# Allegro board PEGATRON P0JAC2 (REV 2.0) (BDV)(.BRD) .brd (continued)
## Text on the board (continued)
L6-GND: list("[Spacing] L6-GND" "43.Microvia to Route Keepout" "0 MIL [DEFAULT]" "OVERLAP" "" "DRC ERROR CLASS/L6-GND" "[Shape] Route Keepout/All ((-570.0 2225.0) (410.0 2765.0))" "[B/BVia] AU_HP_L (VIA10D4A24-L6-L7) (-535.72 2513.77)" list(-532.440000 2510.000000) nil)@@@list("bobo_dong" "2014/01/13 20:47:23" nil "S0DCOA89102" "g1t-p0jac.11")@@@nil | list("[Spacing] L6-GND" "40.Microvia to Route Keepout" "0 MIL [DEFAULT]" "OVERLAP" "" "DRC ERROR CLASS/L6-GND" "[Shape] Route Keepout/All ((-570.0 2225.0) (410.0 2765.0))" "[B/BVia] AGND_AUD (VIA10D4A24-L6-L7) (-535.72 2592.51)" list(-531.380000 2595.000000) nil)@@@list("bobo_dong" "2014/01/13 20:47:18" nil "S0DCOA89102" "g1t-p0jac.11")@@@nil | list("[Spacing] L6-GND" "8.Shape to Route Keepin" "0 MIL [DEFAULT]" "0 MIL" "0.00 MIL" "DRC ERROR CLASS/L6-GND" "[Shape] Route Keepin/All ((-679.03 -19.38) (3281.17 4854.0))" "[L6-Gnd Shape] GND ((-679.11 -19.37) (3281.09 4854.01))" list(-260.500000 4854.000000) nil)@@@nil@@@list("vincent_kuo" "2014/02/26 12:03:45" nil "VINCENT_KUO-PC" "g1t-p0jac_byt-t.14") | list("[Spacing] L6-GND" "3.Shape to Route Keepin" "0 MIL [DEFAULT]" "0 MIL" "0.00 MIL" "DRC ERROR CLASS/L6-GND" "[Shape] Route Keepin/All ((-679.03 -19.38) (3281.17 4854.0))" "[L6-Gnd Shape] GND ((-679.11 -19.37) (3281.09 4854.01))" list(-19.380000 -0.010000) nil)@@@list("bobo_dong" "2014/02/26 15:13:22" nil "S0DCOA89102" "g1t-p0jac.11")@@@list("vincent_kuo" "2014/02/26 15:23:36" nil "VINCENT_KUO-PC" "g1t-p0jac_byt-t.14") | list("[Spacing] L6-GND" "41.Microvia to Route Keepout" "0 MIL [DEFAULT]" "OVERLAP" "" "DRC ERROR CLASS/L6-GND" "[Shape] Route Keepout/All ((-570.0 2225.0) (410.0 2765.0))" "[B/BVia] AGND_AUD (VIA10D4A24-L6-L7) (273.53 2604.1)" list(275.000000 2608.880000) nil)@@@list("bobo_dong" "2014/01/13 20:47:18" nil "S0DCOA89102" "g1t-p0jac.11")@@@nil | list("[Spacing] L6-GND" "42.Thru Via to Route Keepout" "0 MIL [DEFAULT]" "0 MIL" "0.00 MIL" "DRC ERROR CLASS/L6-GND" "[Shape] Route Keepout/All ((-570.0 2225.0) (410.0 2765.0))" "[ThruVia] AU_HP_L (VIA20D10A32) (340.8 2717.6)" list(350.000000 2721.520000) nil)@@@list("bobo_dong" "2014/01/13 20:47:19" nil "S0DCOA89102" "g1t-p0jac.11")@@@nil | list("[Spacing] L6-GND" "37.Line to Route Keepout" "0 MIL [DEFAULT]" "0 MIL" "0.00 MIL" "DRC ERROR CLASS/L6-GND" "[Shape] Route Keepout/All ((155.0 2225.0) (480.0 2457.5))" "[Line] MICBIAS1 ((418.0 2429.68) (427.1 2438.78))" list(420.000000 2431.680000) nil)@@@list("bobo_dong" "2014/01/13 20:47:08" nil "S0DCOA89102" "g1t-p0jac.11")@@@nil | list("[Spacing] L6-GND" "36.Line to Route Keepout" "0 MIL [DEFAULT]" "0 MIL" "0.00 MIL" "DRC ERROR CLASS/L6-GND" "[Shape] Route Keepout/All ((155.0 2225.0) (480.0 2457.5))" "[Line] MICBIAS1 ((418.0 2415.0) (422.0 2433.68))" list(420.000000 2424.340000) nil)@@@list("bobo_dong" "2014/01/13 20:47:05" nil "S0DCOA89102" "g1t-p0jac.11")@@@nil | list("[Spacing] L6-GND" "1.Line to Route Keepout" "0 MIL [DEFAULT]" "0 MIL" "0.00 MIL" "DRC ERROR CLASS/L6-GND" "[Shape] Route Keepout/All ((155.0 2225.0) (480.0 2457.5))" "[Line] MICBIAS1 ((411.0 2408.0) (427.1 2424.1))" list(420.000000 2417.000000) nil)@@@list("bobo_dong" "2014/01/13 20:58:34" nil "S0DCOA89102" "g1t-p0jac.11")@@@nil | list("[Spacing] L6-GND" "35.Line to Route Keepout" "0 MIL [DEFAULT]" "0 MIL" "0.00 MIL" "DRC ERROR CLASS/L6-GND" "[Shape] Route Keepout/All ((155.0 2225.0) (480.0 2457.5))" "[Line] MICBIAS1 ((411.0 2408.0) (422.0 2419.0))" list(420.000000 2417.000000) nil)@@@list("bobo_dong" "2014/01/13 20:47:03" nil "S0DCOA89102" "g1t-p0jac.11")@@@nil | list("[Spacing] L6-GND" "3.BB Via to Route Keepout" "0 MIL [DEFAULT]" "0 MIL" "0.00 MIL" "DRC ERROR CLASS/L6-GND" "[Shape] Route Keepout/All ((155.0 2225.0) (480.0 2457.5))" "[B/BVia] MICBIAS1 (VIA18D8A26-L3-L6) (413.0 2410.0)" list(420.000000 2415.660000) nil)@@@list("bobo_dong" "2014/01/13 20:58:36" nil "S0DCOA89102" "g1t-p0jac.11")@@@nil | list("[Spacing] L6-GND" "39.Microvia to Route Keepout" "0 MIL [DEFAULT]" "0 MIL" "0.00 MIL" "DRC ERROR CLASS/L6-GND" "[Shape] Route Keepout/All ((155.0 2225.0) (480.0 2457.5))" "[B/BVia] MICBIAS1 (VIA10D4A24-L6-L7) (425.1 2436.78)" list(420.950000 2434.000000) nil)@@@list("bobo_dong" "2014/01/13 20:47:17" nil "S0DCOA89102" "g1t-p0jac.11")@@@nil | list("[Spacing] L6-GND" "2.Line to Route Keepout" "0 MIL [DEFAULT]" "0 MIL" "0.00 MIL" "DRC ERROR CLASS/L6-GND" "[Shape] Route Keepout/All ((155.0 2225.0) (480.0 2457.5))" "[Line] MICBIAS1 ((423.1 2420.1) (427.1 2438.78))" list(425.100000 2427.730000) nil)@@@list("bobo_dong" "2014/01/13 20:58:35" nil "S0DCOA89102" "g1t-p0jac.11")@@@nil | list("[Spacing-SameNet] L6-GND" "68.Line to Shape Same Net" "4 MIL [DEFAULT]" "0 MIL" "4.00 MIL" "DRC ERROR CLASS/L6-GND" "[Line] GND ((1181.5 2923.5) (1191.5 2935.5))" "[L6-Gnd Shape] GND ((1179.11 2932.53) (1197.86 2957.97))" list(1190.000000 2934.000000) nil)@@@list("jennifer_hsu" "2014/01/14 11:36:27" nil "JENNIFER_H-PC" "g1t-p0jac_byt-t.11")@@@list("doris_chen" "2014/01/16 14:59:34" nil "JULIA_YU-PC1" "g1t-p0jac_byt-t.13-chk") | list("[Spacing-SameNet] L6-GND" "69.Line to Line Same Net" "4 MIL [DEFAULT]" "3.08 MIL" "0.92 MIL" "DRC ERROR CLASS/L6-GND" "[Line] GND ((1267.5 2921.5) (1273.5 2935.5))" "[Line] GND ((1269.5 2938.5) (1275.5 2953.5))" list(1272.000000 2934.000000) nil)@@@list("vincent_kuo" "2014/01/14 11:44:14" nil "VINCENT_KUO-PC" "g1t-p0jac_byt-t.11")@@@list("doris_chen" "2014/01/16 14:59:47" nil "JULIA_YU-PC1" "g1t-p0jac_byt-t.13-chk") | list("[Spacing-SameNet] L6-GND" "71.Line to Line Same Net" "4 MIL [DEFAULT]" "0 MIL" "4.00 MIL" "DRC ERROR CLASS/L6-GND" "[Line] GND ((1766.5 3728.5) (1776.5 3732.5))" "[Line] GND ((1764.5 3714.5) (1767.5 3729.5))" list(1768.000000 3730.000000) nil)@@@list("jennifer_hsu" "2014/01/14 11:36:30" nil "JENNIFER_H-PC" "g1t-p0jac_byt-t.11")@@@list("doris_chen" "2014/01/16 14:59:49" nil "JULIA_YU-PC1" "g1t-p0jac_byt-t.13-chk") | list("[Spacing-SameNet] L6-GND" "70.Line to Line Same Net" "4 MIL [DEFAULT]" "0 MIL" "4.00 MIL" "DRC ERROR CLASS/L6-GND" "[Line] GND ((1941.69 3513.69) (1944.69 3547.5))" "[Line] GND ((1941.5 3510.5) (1944.5 3516.5))" list(1943.190000 3515.190000) nil)@@@list("jennifer_hsu" "2014/01/14 11:36:28" nil "JENNIFER_H-PC" "g1t-p0jac_byt-t.11")@@@list("doris_chen" "2014/01/16 14:59:48" nil "JULIA_YU-PC1" "g1t-p0jac_byt-t.13-chk") | list("[Spacing] L6-GND" "8.Shape to Route Keepin" "0 MIL [DEFAULT]" "0 MIL" "0.00 MIL" "DRC ERROR CLASS/L6-GND" "[Shape] Route Keepin/All ((-679.11 -19.37) (3281.09 4854.01))" "[L6-Gnd Shape] GND ((-679.11 -19.37) (3281.09 4854.01))" list(3104.240000 2379.050000) nil)@@@list("bobo_dong" "2014/01/13 20:47:03" nil "S0DCOA89102" "g1t-p0jac.11")@@@list("vincent_kuo" "2014/01/13 22:06:22" nil "VINCENT_KUO-PC" "g1t-p0jac_byt-t.11") | list("[Spacing] L6-GND" "22.Shape to Route Keepin" "0 MIL [DEFAULT]" "0 MIL" "0.00 MIL" "DRC ERROR CLASS/L6-GND" "[Shape] Route Keepin/All ((-679.11 -19.37) (3281.09 4854.01))" "[L6-Gnd Shape] GND ((-679.11 -19.37) (3281.09 4854.01))" list(3173.920000 1359.560000) nil)@@@list("bobo_dong" "2014/01/15 10:39:16" nil "S0DCOA89102" "g1t-p0jac.11")@@@nil | list("[Spacing] L6-GND" "6.Shape to Route Keepin" "0 MIL [DEFAULT]" "0 MIL" "0.00 MIL" "DRC ERROR CLASS/L6-GND" "[Shape] Route Keepin/All ((-679.11 -19.37) (3281.09 4854.01))" "[L6-Gnd Shape] GND ((-679.11 -19.37) (3281.09 4854.01))" list(3189.060000 1979.830000) nil)@@@list("vincent_kuo" "2014/01/15 11:14:29" nil "VINCENT_KUO-PC" "g1t-p0jac_byt-t.12")@@@list("doris_chen" "2014/01/16 14:58:56" nil "JULIA_YU-PC1" "g1t-p0jac_byt-t.13-chk") | list("[Spacing] L6-GND" "4.Thru Via to Route Keepin" "0 MIL [DEFAULT]" "1689.77 MIL" "-1689.77 MIL" "DRC ERROR CLASS/L6-GND" "[Shape] Route Keepin/All ((-2611.73 -1560.75) (2448.51 1842.01))" "[ThruVia] Dummy (VIA20D10A32) (-2910.0 -2405.0)" list(-2599.980000 -733.740000) nil)@@@list("sky_zheng" "2013/09/13 10:57:17" nil "RDD_704_PC" "g1t-oxygen.10")@@@list("andy_lien" "2013/09/13 12:15:13" nil "ANDY_LIEN-PC" "g1t-oxygen.10") | list("[Spacing] L6-GND" "3.Thru Via to Route Keepin" "0 MIL [DEFAULT]" "1713.38 MIL" "-1713.38 MIL" "DRC ERROR CLASS/L6-GND" "[Shape] Route Keepin/All ((-2611.73 -1560.75) (2448.51 1842.01))" "[ThruVia] Dummy (VIA20D10A32) (-2910.0 -2429.0)" list(-2599.940000 -733.750000) nil)@@@list("sky_zheng" "2013/09/13 10:57:18" nil "RDD_704_PC" "g1t-oxygen.10")@@@list("andy_lien" "2013/09/13 12:15:12" nil "ANDY_LIEN-PC" "g1t-oxygen.10") | list("[Spacing] L6-GND" "2.BB Via to Route Keepin" "0 MIL [DEFAULT]" "2040.83 MIL" "-2040.83 MIL" "DRC ERROR CLASS/L6-GND" "[Shape] Route Keepin/All ((-2611.73 -1560.75) (2448.51 1842.01))" "[B/BVia] Dummy (VIA18D8A26-L3-L6) (-2910.0 -2760.0)" list(-2599.530000 -733.810000) nil)@@@list("sky_zheng" "2013/09/13 10:57:19" nil "RDD_704_PC" "g1t-oxygen.10")@@@list("andy_lien" "2013/09/13 12:15:12" nil "ANDY_LIEN-PC" "g1t-oxygen.10") | list("[Spacing] L6-GND" "1.BB Via to Route Keepin" "0 MIL [DEFAULT]" "2062.58 MIL" "-2062.58 MIL" "DRC ERROR CLASS/L6-GND" "[Shape] Route Keepin/All ((-2611.73 -1560.75) (2448.51 1842.01))" "[B/BVia] Dummy (VIA18D8A26-L3-L6) (-2910.0 -2782.0)" list(-2599.510000 -733.820000) nil)@@@list("sky_zheng" "2013/09/13 10:57:20" nil "RDD_704_PC" "g1t-oxygen.10")@@@list("andy_lien" "2013/09/13 12:15:12" nil "ANDY_LIEN-PC" "g1t-oxygen.10")
L7-SIG: list("[Spacing] L7-SIG" "63.Microvia to Route Keepout" "0 MIL [DEFAULT]" "OVERLAP" "" "DRC ERROR CLASS/L7-SIG" "[Shape] Route Keepout/All ((-570.0 2225.0) (410.0 2765.0))" "[B/BVia] AU_HP_L (VIA10D4A24-L6-L7) (-535.72 2513.77)" list(-532.440000 2510.000000) nil)@@@list("bobo_dong" "2014/01/13 20:48:21" nil "S0DCOA89102" "g1t-p0jac.11")@@@nil | list("[Spacing] L7-SIG" "64.Microvia to Route Keepout" "0 MIL [DEFAULT]" "0 MIL" "0.00 MIL" "DRC ERROR CLASS/L7-SIG" "[Shape] Route Keepout/All ((-570.0 2225.0) (410.0 2765.0))" "[B/BVia] AU_HP_L (VIA10D4A24-L7-BOT) (-535.72 2513.77)" list(-532.440000 2510.000000) nil)@@@list("bobo_dong" "2014/01/13 20:48:22" nil "S0DCOA89102" "g1t-p0jac.11")@@@nil | list("[Spacing] L7-SIG" "57.Microvia to Route Keepout" "0 MIL [DEFAULT]" "OVERLAP" "" "DRC ERROR CLASS/L7-SIG" "[Shape] Route Keepout/All ((-570.0 2225.0) (410.0 2765.0))" "[B/BVia] AGND_AUD (VIA10D4A24-L7-BOT) (-535.72 2592.51)" list(-531.380000 2595.000000) nil)@@@list("bobo_dong" "2014/01/13 20:48:16" nil "S0DCOA89102" "g1t-p0jac.11")@@@nil | list("[Spacing] L7-SIG" "58.Microvia to Route Keepout" "0 MIL [DEFAULT]" "OVERLAP" "" "DRC ERROR CLASS/L7-SIG" "[Shape] Route Keepout/All ((-570.0 2225.0) (410.0 2765.0))" "[B/BVia] AGND_AUD (VIA10D4A24-L6-L7) (-535.72 2592.51)" list(-531.380000 2595.000000) nil)@@@list("bobo_dong" "2014/01/13 20:48:16" nil "S0DCOA89102" "g1t-p0jac.11")@@@nil | list("[Spacing] L7-SIG" "67.Line to Route Keepout" "0 MIL [DEFAULT]" "0 MIL" "0.00 MIL" "DRC ERROR CLASS/L7-SIG" "[Shape] Route Keepout/All ((-570.0 2225.0) (410.0 2765.0))" "[Line] +V1P8S ((-573.0 2450.0) (-466.02 2556.98))" list(-513.000000 2510.000000) nil)@@@list("bobo_dong" "2014/01/13 20:48:24" nil "S0DCOA89102" "g1t-p0jac.11")@@@nil | list("[Spacing] L7-SIG" "4.Line to Route Keepout" "0 MIL [DEFAULT]" "0 MIL" "0.00 MIL" "DRC ERROR CLASS/L7-SIG" "[Shape] Route Keepout/L7-Sig ((-570.0 2230.0) (401.57 2765.0))" "[Line] +V1P8S ((-561.98 2457.02) (-461.22 2557.78))" list(-513.000000 2506.000000) nil)@@@list("bobo_dong" "2014/02/27 14:43:49" nil "S0DCOA89102" "g1t-p0jac.11")@@@list("vincent_kuo" "2014/02/27 14:51:25" nil "VINCENT_KUO-PC" "g1t-p0jac_byt-t.14") | list("[Spacing] L7-SIG" "9.Line to Route Keepout" "0 MIL [DEFAULT]" "0 MIL" "0.00 MIL" "DRC ERROR CLASS/L7-SIG" "[Shape] Route Keepout/L7-Sig ((-570.0 2225.0) (401.57 2765.0))" "[Line] +V1P8S ((-561.98 2457.02) (-461.22 2557.78))" list(-513.000000 2506.000000) nil)@@@list("bobo_dong" "2014/02/25 09:08:24" nil "s0dcoa89102" "g1t-p0jac.11")@@@list("vincent_kuo" "2014/02/26 12:03:48" nil "VINCENT_KUO-PC" "g1t-p0jac_byt-t.14") | list("[Spacing] L7-SIG" "7.Shape to Route Keepin" "0 MIL [DEFAULT]" "0 MIL" "0.00 MIL" "DRC ERROR CLASS/L7-SIG" "[Shape] Route Keepin/All ((-679.03 -19.38) (3281.17 4854.0))" "[L7-Sig Shape] GND ((-679.11 -19.37) (3281.09 4854.01))" list(-19.380000 -0.010000) nil)@@@list("bobo_dong" "2014/02/26 15:13:23" nil "S0DCOA89102" "g1t-p0jac.11")@@@list("vincent_kuo" "2014/02/26 12:03:49" nil "VINCENT_KUO-PC" "g1t-p0jac_byt-t.14") | list("[Spacing] L7-SIG" "65.Line to Route Keepout" "0 MIL [DEFAULT]" "0 MIL" "0.00 MIL" "DRC ERROR CLASS/L7-SIG" "[Shape] Route Keepout/All ((-570.0 2225.0) (410.0 2765.0))" "[Line] N55582751 ((184.6 2551.85) (278.53 2561.85))" list(273.530000 2556.850000) nil)@@@list("bobo_dong" "2014/01/13 20:48:23" nil "S0DCOA89102" "g1t-p0jac.11")@@@nil | list("[Spacing] L7-SIG" "59.Microvia to Route Keepout" "0 MIL [DEFAULT]" "OVERLAP" "" "DRC ERROR CLASS/L7-SIG" "[Shape] Route Keepout/All ((-570.0 2225.0) (410.0 2765.0))" "[B/BVia] AGND_AUD (VIA10D4A24-L6-L7) (273.53 2604.1)" list(275.000000 2608.880000) nil)@@@list("bobo_dong" "2014/01/13 20:48:17" nil "S0DCOA89102" "g1t-p0jac.11")@@@nil | list("[Spacing] L7-SIG" "60.Microvia to Route Keepout" "0 MIL [DEFAULT]" "OVERLAP" "" "DRC ERROR CLASS/L7-SIG" "[Shape] Route Keepout/All ((-570.0 2225.0) (410.0 2765.0))" "[B/BVia] AGND_AUD (VIA10D4A24-L7-BOT) (273.53 2604.1)" list(275.000000 2608.880000) nil)@@@list("bobo_dong" "2014/01/13 20:48:19" nil "S0DCOA89102" "g1t-p0jac.11")@@@nil | list("[Spacing] L7-SIG" "66.Microvia to Route Keepout" "0 MIL [DEFAULT]" "0 MIL" "0.00 MIL" "DRC ERROR CLASS/L7-SIG" "[Shape] Route Keepout/All ((-570.0 2225.0) (410.0 2765.0))" "[B/BVia] N55582751 (VIA10D4A24-L7-BOT) (273.53 2556.85)" list(275.000000 2561.630000) nil)@@@list("bobo_dong" "2014/01/13 20:48:23" nil "S0DCOA89102" "g1t-p0jac.11")@@@nil | list("[Spacing] L7-SIG" "62.Thru Via to Route Keepout" "0 MIL [DEFAULT]" "0 MIL" "0.00 MIL" "DRC ERROR CLASS/L7-SIG" "[Shape] Route Keepout/All ((-570.0 2225.0) (410.0 2765.0))" "[ThruVia] AU_HP_L (VIA20D10A32) (340.8 2717.6)" list(350.000000 2721.520000) nil)@@@list("bobo_dong" "2014/01/13 20:48:20" nil "S0DCOA89102" "g1t-p0jac.11")@@@nil | list("[Spacing] L7-SIG" "51.Line to Route Keepout" "0 MIL [DEFAULT]" "0 MIL" "0.00 MIL" "DRC ERROR CLASS/L7-SIG" "[Shape] Route Keepout/All ((-570.0 2225.0) (410.0 2765.0))" "[Line] DMIC1_DAT ((404.35 2431.78) (414.35 2462.35))" list(409.350000 2437.500000) nil)@@@list("bobo_dong" "2014/01/13 20:48:11" nil "S0DCOA89102" "g1t-p0jac.11")@@@nil | list("[Spacing] L7-SIG" "52.Line to Route Keepout" "0 MIL [DEFAULT]" "0 MIL" "0.00 MIL" "DRC ERROR CLASS/L7-SIG" "[Shape] Route Keepout/All ((155.0 2225.0) (480.0 2457.5))" "[Line] DMIC1_DAT ((404.35 2431.78) (414.35 2462.35))" list(409.350000 2437.500000) nil)@@@list("bobo_dong" "2014/01/13 20:48:11" nil "S0DCOA89102" "g1t-p0jac.11")@@@nil | list("[Spacing] L7-SIG" "53.Line to Route Keepout" "0 MIL [DEFAULT]" "0 MIL" "0.00 MIL" "DRC ERROR CLASS/L7-SIG" "[Shape] Route Keepout/All ((-570.0 2225.0) (410.0 2765.0))" "[Line] DMIC1_DAT ((404.35 2452.35) (481.31 2529.31))" list(409.500000 2457.500000) nil)@@@list("bobo_dong" "2014/01/13 20:48:12" nil "S0DCOA89102" "g1t-p0jac.11")@@@nil | list("[Spacing] L7-SIG" "54.Line to Route Keepout" "0 MIL [DEFAULT]" "0 MIL" "0.00 MIL" "DRC ERROR CLASS/L7-SIG" "[Shape] Route Keepout/All ((155.0 2225.0) (480.0 2457.5))" "[Line] DMIC1_DAT ((404.35 2452.35) (481.31 2529.31))" list(409.500000 2457.500000) nil)@@@list("bobo_dong" "2014/01/13 20:48:13" nil "S0DCOA89102" "g1t-p0jac.11")@@@nil | list("[Spacing] L7-SIG" "55.Microvia to Route Keepout" "0 MIL [DEFAULT]" "0 MIL" "0.00 MIL" "DRC ERROR CLASS/L7-SIG" "[Shape] Route Keepout/All ((-570.0 2225.0) (410.0 2765.0))" "[B/BVia] DMIC1_DAT (VIA10D4A24-L7-BOT) (409.35 2436.78)" list(410.000000 2441.740000) nil)@@@list("bobo_dong" "2014/01/13 20:48:14" nil "S0DCOA89102" "g1t-p0jac.11")@@@nil | list("[Spacing] L7-SIG" "56.Microvia to Route Keepout" "0 MIL [DEFAULT]" "0 MIL" "0.00 MIL" "DRC ERROR CLASS/L7-SIG" "[Shape] Route Keepout/All ((155.0 2225.0) (480.0 2457.5))" "[B/BVia] DMIC1_DAT (VIA10D4A24-L7-BOT) (409.35 2436.78)" list(414.300000 2437.500000) nil)@@@list("bobo_dong" "2014/01/13 20:48:14" nil "S0DCOA89102" "g1t-p0jac.11")@@@nil | list("[Spacing] L7-SIG" "47.Microvia to Route Keepout" "0 MIL [DEFAULT]" "0 MIL" "0.00 MIL" "DRC ERROR CLASS/L7-SIG" "[Shape] Route Keepout/All ((155.0 2225.0) (480.0 2457.5))" "[B/BVia] MICBIAS1 (VIA10D4A24-L6-L7) (425.1 2436.78)" list(420.950000 2434.000000) nil)@@@list("bobo_dong" "2014/01/13 20:48:05" nil "S0DCOA89102" "g1t-p0jac.11")@@@nil | list("[Spacing] L7-SIG" "48.Microvia to Route Keepout" "0 MIL [DEFAULT]" "0 MIL" "0.00 MIL" "DRC ERROR CLASS/L7-SIG" "[Shape] Route Keepout/All ((155.0 2225.0) (480.0 2457.5))" "[B/BVia] MICBIAS1 (VIA10D4A24-L7-BOT) (425.1 2436.78)" list(420.950000 2434.000000) nil)@@@list("bobo_dong" "2014/01/13 20:48:07" nil "S0DCOA89102" "g1t-p0jac.11")@@@nil | list("[Spacing] L7-SIG" "61.Line to Route Keepout" "0 MIL [DEFAULT]" "0 MIL" "0.00 MIL" "DRC ERROR CLASS/L7-SIG" "[Shape] Route Keepout/All ((155.0 2225.0) (480.0 2457.5))" "[Line] +V1P8S_AUD_D ((450.0 2328.0) (583.17 2338.0))" list(460.000000 2333.000000) nil)@@@list("bobo_dong" "2014/01/13 20:48:20" nil "S0DCOA89102" "g1t-p0jac.11")@@@nil | list("[Spacing] L7-SIG" "50.Line to Route Keepout" "0 MIL [DEFAULT]" "0 MIL" "0.00 MIL" "DRC ERROR CLASS/L7-SIG" "[Shape] Route Keepout/All ((155.0 2225.0) (480.0 2457.5))" "[Line] JACK_DET# ((415.98 2255.98) (476.0 2316.0))" list(460.000000 2300.000000) nil)@@@list("bobo_dong" "2014/01/13 20:48:10" nil "S0DCOA89102" "g1t-p0jac.11")@@@nil | list("[Spacing] L7-SIG" "49.Line to Route Keepout" "0 MIL [DEFAULT]" "0 MIL" "0.00 MIL" "DRC ERROR CLASS/L7-SIG" "[Shape] Route Keepout/All ((155.0 2225.0) (480.0 2457.5))" "[Line] JACK_DET# ((466.0 2306.0) (622.0 2316.0))" list(480.000000 2311.000000) nil)@@@list("bobo_dong" "2014/01/13 20:48:09" nil "S0DCOA89102" "g1t-p0jac.11")@@@nil | list("[Spacing] L7-SIG" "4.Shape to Route Keepout" "0 MIL [DEFAULT]" "0 MIL" "0.00 MIL" "DRC ERROR CLASS/L7-SIG" "[Shape] Route Keepout/All ((3056.9 2031.81) (3317.13 2375.11))" "[L7-Sig Shape] GND ((-679.11 -19.37) (3281.09 4854.01))" list(3073.180000 2366.980000) nil)@@@list("bobo_dong" "2014/01/13 20:58:39" nil "S0DCOA89102" "g1t-p0jac.11")@@@nil | list("[Spacing] L7-SIG" "5.Shape to Route Keepin" "0 MIL [DEFAULT]" "0 MIL" "0.00 MIL" "DRC ERROR CLASS/L7-SIG" "[Shape] Route Keepin/All ((-679.11 -19.37) (3281.09 4854.01))" "[L7-Sig Shape] GND ((-679.11 -19.37) (3281.09 4854.01))" list(3081.540000 2036.160000) nil)@@@list("bobo_dong" "2014/02/25 09:08:16" nil "s0dcoa89102" "g1t-p0jac.11")@@@nil | list("[Spacing] L7-SIG" "4.Shape to Route Keepin" "0 MIL [DEFAULT]" "0 MIL" "0.00 MIL" "DRC ERROR CLASS/L7-SIG" "[Shape] Route Keepin/All ((-679.11 -19.37) (3281.09 4854.01))" "[L7-Sig Shape] GND ((-679.11 -19.37) (3281.09 4854.01))" list(3104.240000 2379.050000) nil)@@@list("kelly_lv" "2014/01/14 09:49:42" nil "PC-0005358" "5k-castle.105")@@@list("vincent_kuo" "2014/01/13 22:06:48" nil "VINCENT_KUO-PC" "g1t-p0jac_byt-t.11") | list("[Spacing] L7-SIG" "46.Shape to Route Keepin" "0 MIL [DEFAULT]" "0 MIL" "0.00 MIL" "DRC ERROR CLASS/L7-SIG" "[Shape] Route Keepin/All ((-679.11 -19.37) (3281.09 4854.01))" "[L7-Sig Shape] GND ((-679.11 -19.37) (3281.09 4854.01))" list(3121.440000 1684.960000) nil)@@@list("bobo_dong" "2014/01/13 20:48:04" nil "S0DCOA89102" "g1t-p0jac.11")@@@nil | list("[Spacing] L7-SIG" "6.Shape to Route Keepin" "0 MIL [DEFAULT]" "0 MIL" "0.00 MIL" "DRC ERROR CLASS/L7-SIG" "[Shape] Route Keepin/All ((-679.11 -19.37) (3281.09 4854.01))" "[L7-Sig Shape] GND ((-679.11 -19.37) (3281.09 4854.01))" list(3177.200000 1404.800000) nil)@@@list("bobo_dong" "2014/02/25 14:28:30" nil "S0DCOA89102" "g1t-p0jac.11")@@@nil | list("[Spacing] L7-SIG" "10.Shape to Route Keepin" "0 MIL [DEFAULT]" "0 MIL" "0.00 MIL" "DRC ERROR CLASS/L7-SIG" "[Shape] Route Keepin/All ((-679.11 -19.37) (3281.09 4854.01))" "[L7-Sig Shape] GND ((-679.11 -19.37) (3281.09 4854.01))" list(3189.060000 1979.830000) nil)@@@list("bobo_dong" "2014/01/27 15:50:36" nil "s0dcoa89102" "g1t-p0jac.11")@@@list("doris_chen" "2014/01/16 14:58:58" nil "JULIA_YU-PC1" "g1t-p0jac_byt-t.13-chk") | list("[Spacing] L7-SIG" "45.Shape to Route Keepout" "0 MIL [DEFAULT]" "0 MIL" "0.00 MIL" "DRC ERROR CLASS/L7-SIG" "[Shape] Route Keepout/All ((3220.45 3611.18) (3297.22 3837.56))" "[L7-Sig Shape] GND ((-679.11 -19.37) (3281.09 4854.01))" list(3281.090000 3837.560000) nil)@@@list("bobo_dong" "2014/01/13 20:48:03" nil "S0DCOA89102" "g1t-p0jac.11")@@@nil | list("[Spacing] L7-SIG" "5.Thru Via to Route Keepin" "0 MIL [DEFAULT]" "1689.77 MIL" "-1689.77 MIL" "DRC ERROR CLASS/L7-SIG" "[Shape] Route Keepin/All ((-2611.73 -1560.75) (2448.51 1842.01))" "[ThruVia] Dummy (VIA20D10A32) (-2910.0 -2405.0)" list(-2599.980000 -733.740000) nil)@@@list("sky_zheng" "2013/09/13 10:57:25" nil "RDD_704_PC" "g1t-oxygen.10")@@@list("andy_lien" "2013/09/13 12:15:17" nil "ANDY_LIEN-PC" "g1t-oxygen.10") | list("[Spacing] L7-SIG" "4.Thru Via to Route Keepin" "0 MIL [DEFAULT]" "1713.38 MIL" "-1713.38 MIL" "DRC ERROR CLASS/L7-SIG" "[Shape] Route Keepin/All ((-2611.73 -1560.75) (2448.51 1842.01))" "[ThruVia] Dummy (VIA20D10A32) (-2910.0 -2429.0)" list(-2599.940000 -733.750000) nil)@@@list("sky_zheng" "2013/09/13 10:57:26" nil "RDD_704_PC" "g1t-oxygen.10")@@@list("andy_lien" "2013/09/13 12:15:17" nil "ANDY_LIEN-PC" "g1t-oxygen.10") | list("[Spacing] L7-SIG" "2.Shape to Route Keepin" "0 MIL [DEFAULT]" "0 MIL" "0.00 MIL" "DRC ERROR CLASS/L7-SIG" "[Shape] Route Keepin/All ((-2611.73 -1560.75) (2448.51 1842.01))" "[L7-Sig Shape] GND ((-2611.73 387.71) (-2231.34 1802.64))" list(-2513.300000 391.700000) nil)@@@list("sky_zheng" "2013/09/13 10:57:24" nil "RDD_704_PC" "g1t-oxygen.10")@@@list("andy_lien" "2013/09/13 12:15:15" nil "ANDY_LIEN-PC" "g1t-oxygen.10") | list("[Spacing] L7-SIG" "1.Shape to Route Keepin" "0 MIL [DEFAULT]" "0 MIL" "0.00 MIL" "DRC ERROR CLASS/L7-SIG" "[Shape] Route Keepin/All ((-2611.73 -1560.75) (2448.51 1842.01))" "[L7-Sig Shape] GND ((-2199.6 1385.1) (-2005.01 1752.87))" list(-2195.600000 1424.680000) nil)@@@list("sky_zheng" "2013/09/13 10:57:22" nil "RDD_704_PC" "g1t-oxygen.10")@@@list("andy_lien" "2013/09/13 12:15:15" nil "ANDY_LIEN-PC" "g1t-oxygen.10") | list("[Spacing] L7-SIG" "3.Shape to Route Keepin" "0 MIL [DEFAULT]" "0 MIL" "0.00 MIL" "DRC ERROR CLASS/L7-SIG" "[Shape] Route Keepin/All ((-2611.73 -1560.75) (2448.51 1842.01))" "[L7-Sig Shape] GND ((-2611.73 -1560.75) (2448.51 1842.01))" list(-13.300000 -778.660000) nil)@@@list("sky_zheng" "2013/09/13 10:57:24" nil "RDD_704_PC" "g1t-oxygen.10")@@@list("andy_lien" "2013/09/13 12:15:16" nil "ANDY_LIEN-PC" "g1t-oxygen.10") | list("[Spacing] L7-SIG" "50.Shape to Route Keepout" "0 MIL [DEFAULT]" "0 MIL" "0.00 MIL" "DRC ERROR CLASS/L7-SIG" "[Shape] Route Keepout/All ((190.63 -1315.47) (634.34 -438.7))" "[L7-Sig Shape] GND ((170.63 -1335.48) (654.34 -418.71))" list(190.630000 -495.210000) nil)@@@list("sky_zheng" "2013/09/13 10:57:21" nil "RDD_704_PC" "g1t-oxygen.10")@@@nil | list("[Spacing] L7-SIG" "51.Shape to Route Keepout" "0 MIL [DEFAULT]" "0 MIL" "0.00 MIL" "DRC ERROR CLASS/L7-SIG" "[Shape] Route Keepout/All ((184.14 -1363.31) (414.46 -390.87))" "[L7-Sig Shape] GND ((170.63 -1335.48) (654.34 -418.71))" list(390.830000 -418.710000) nil)@@@list("sky_zheng" "2013/09/13 10:57:22" nil "RDD_704_PC" "g1t-oxygen.10")@@@nil
User.7: list("[Package] BOTTOM" "95.Sym Soldermask to Pad Soldermask Spacing" "6.7 MIL [SOLDERMASK_SPACING]" "0 MIL" "6.70 MIL" "DRC ERROR CLASS/SOLDERMASK_TOP" "[ThruPin] Dummy (<uTiL>cId4362<uTiL>.1) (-144.19 4584.63)" "[Shape] Package Geometry/Soldermask_Top ((-262.3 4419.29) (-0.49 4677.16))" list(-144.190000 4665.250000) nil)@@@list("bobo_dong" "2014/01/13 20:57:14" nil "S0DCOA89102" "g1t-p0jac.11")@@@list("vincent_kuo" "2014/01/13 22:18:57" nil "VINCENT_KUO-PC" "g1t-p0jac_byt-t.11") | list("[Package] BOTTOM" "97.Sym Soldermask to Sym Soldermask Spacing" "6.7 MIL [SOLDERMASK_SPACING]" "0 MIL" "6.70 MIL" "DRC ERROR CLASS/SOLDERMASK_TOP" "[Shape] Package Geometry/Soldermask_Top ((2887.7 4005.9) (3163.29 4282.67))" "[Shape] Package Geometry/Soldermask_Top ((2887.65 4005.82) (3163.24 4282.59))" list(2887.700000 4282.590000) nil)@@@list("bobo_dong" "2014/01/13 20:57:19" nil "S0DCOA89102" "g1t-p0jac.11")@@@list("vincent_kuo" "2014/01/13 22:19:00" nil "VINCENT_KUO-PC" "g1t-p0jac_byt-t.11") | list("[Package] BOTTOM" "160.Pad Soldermask to Pad Soldermask Spacing" "6.7 MIL [SOLDERMASK_SPACING]" "6.5 MIL" "0.20 MIL" "DRC ERROR CLASS/SOLDERMASK_TOP" "[ThruPin] HDMI_CLK_DP_CON (<uTiL>cId2273<uTiL>.12) (2998.02 1529.13)" "[ThruPin] HDMI_DATA1_DN_CON (<uTiL>cId2273<uTiL>.8) (2998.02 1560.63)" list(2998.020000 1560.630000) nil)@@@list("bobo_dong" "2014/01/13 20:57:13" nil "S0DCOA89102" "g1t-p0jac.11")@@@list("doris_chen" "2014/01/16 15:00:17" nil "JULIA_YU-PC1" "g1t-p0jac_byt-t.13-chk") | list("[Package] BOTTOM" "33.Pad Soldermask to Pad Soldermask Spacing" "6.7 MIL [SOLDERMASK_SPACING]" "6.49 MIL" "0.21 MIL" "DRC ERROR CLASS/SOLDERMASK_TOP" "[ThruPin] GND (<uTiL>cId2273<uTiL>.4) (2998.02 1592.12)" "[ThruPin] HDMI_DATA1_DN_CON (<uTiL>cId2273<uTiL>.8) (2998.02 1560.63)" list(2998.020000 1560.630000) nil)@@@list("bobo_dong" "2014/01/13 20:57:12" nil "S0DCOA89102" "g1t-p0jac.11")@@@list("vincent_kuo" "2014/01/13 22:31:49" nil "VINCENT_KUO-PC" "g1t-p0jac_byt-t.11") | list("[Package] BOTTOM" "32.Pad Soldermask to Pad Soldermask Spacing" "6.7 MIL [SOLDERMASK_SPACING]" "6.49 MIL" "0.21 MIL" "DRC ERROR CLASS/SOLDERMASK_TOP" "[ThruPin] GND (<uTiL>cId2273<uTiL>.16) (2998.02 1497.64)" "[ThruPin] HDMI_CLK_DP_CON (<uTiL>cId2273<uTiL>.12) (2998.02 1529.13)" list(2998.020000 1529.130000) nil)@@@list("bobo_dong" "2014/01/13 20:57:08" nil "S0DCOA89102" "g1t-p0jac.11")@@@list("vincent_kuo" "2014/01/13 22:31:48" nil "VINCENT_KUO-PC" "g1t-p0jac_byt-t.11") | list("[Package] BOTTOM" "94.Sym Soldermask to Pad Soldermask Spacing" "6.7 MIL [SOLDERMASK_SPACING]" "0.14 MIL" "6.56 MIL" "DRC ERROR CLASS/SOLDERMASK_TOP" "[Shape] Package Geometry/Soldermask_Top ((2887.7 4005.9) (3163.29 4282.67))" "[ThruPin] Dummy (<uTiL>cId4197<uTiL>.1) (3045.29 3946.76)" list(3045.290000 4005.900000) nil)@@@list("bobo_dong" "2014/01/13 20:57:06" nil "S0DCOA89102" "g1t-p0jac.11")@@@list("vincent_kuo" "2014/01/13 22:18:54" nil "VINCENT_KUO-PC" "g1t-p0jac_byt-t.11") | list("[Package] BOTTOM" "30.Pad Soldermask to Pad Soldermask Spacing" "6.7 MIL [SOLDERMASK_SPACING]" "6.49 MIL" "0.21 MIL" "DRC ERROR CLASS/SOLDERMASK_TOP" "[ThruPin] Dummy (<uTiL>cId2273<uTiL>.2) (3061.01 1607.87)" "[ThruPin] HDMI_DATA1_DP_CON (<uTiL>cId2273<uTiL>.6) (3061.01 1576.38)" list(3061.010000 1576.380000) nil)@@@list("bobo_dong" "2014/01/13 20:57:10" nil "S0DCOA89102" "g1t-p0jac.11")@@@list("vincent_kuo" "2014/01/13 22:31:42" nil "VINCENT_KUO-PC" "g1t-p0jac_byt-t.11") | list("[Package] BOTTOM" "31.Pad Soldermask to Pad Soldermask Spacing" "6.7 MIL [SOLDERMASK_SPACING]" "6.5 MIL" "0.20 MIL" "DRC ERROR CLASS/SOLDERMASK_TOP" "[ThruPin] GND (<uTiL>cId2273<uTiL>.10) (3061.01 1544.88)" "[ThruPin] HDMI_DATA1_DP_CON (<uTiL>cId2273<uTiL>.6) (3061.01 1576.38)" list(3061.010000 1576.380000) nil)@@@list("bobo_dong" "2014/01/13 20:57:11" nil "S0DCOA89102" "g1t-p0jac.11")@@@list("vincent_kuo" "2014/01/13 22:31:44" nil "VINCENT_KUO-PC" "g1t-p0jac_byt-t.11") | list("[Package] BOTTOM" "28.Pad Soldermask to Pad Soldermask Spacing" "6.7 MIL [SOLDERMASK_SPACING]" "6.5 MIL" "0.20 MIL" "DRC ERROR CLASS/SOLDERMASK_TOP" "[ThruPin] GND (<uTiL>cId2273<uTiL>.10) (3061.01 1544.88)" "[ThruPin] HDMI_CLK_DN_CON (<uTiL>cId2273<uTiL>.14) (3061.01 1513.38)" list(3061.010000 1513.380000) nil)@@@list("bobo_dong" "2014/01/13 20:57:07" nil "S0DCOA89102" "g1t-p0jac.11")@@@list("vincent_kuo" "2014/01/13 22:31:41" nil "VINCENT_KUO-PC" "g1t-p0jac_byt-t.11") | list("[Package] BOTTOM" "29.Pad Soldermask to Pad Soldermask Spacing" "6.7 MIL [SOLDERMASK_SPACING]" "6.49 MIL" "0.21 MIL" "DRC ERROR CLASS/SOLDERMASK_TOP" "[ThruPin] HDMI_CLK_DN_CON (<uTiL>cId2273<uTiL>.14) (3061.01 1513.38)" "[ThruPin] HDMI_DDC_SDA_CONN (<uTiL>cId2273<uTiL>.18) (3061.01 1481.89)" list(3061.010000 1481.890000) nil)@@@list("bobo_dong" "2014/01/13 20:57:08" nil "S0DCOA89102" "g1t-p0jac.11")@@@list("vincent_kuo" "2014/01/13 22:31:41" nil "VINCENT_KUO-PC" "g1t-p0jac_byt-t.11") | list("[Package] BOTTOM" "96.Sym Soldermask to Pad Soldermask Spacing" "6.7 MIL [SOLDERMASK_SPACING]" "0 MIL" "6.70 MIL" "DRC ERROR CLASS/SOLDERMASK_TOP" "[ThruPin] Dummy (<uTiL>cId4361<uTiL>.1) (3045.18 4149.6)" "[Shape] Package Geometry/Soldermask_Top ((2887.65 4005.82) (3163.24 4282.59))" list(3151.380000 4149.600000) nil)@@@list("bobo_dong" "2014/01/13 20:57:15" nil "S0DCOA89102" "g1t-p0jac.11")@@@list("vincent_kuo" "2014/01/13 22:18:58" nil "VINCENT_KUO-PC" "g1t-p0jac_byt-t.11") | list("[Package] BOTTOM" "76.Pad Soldermask to Pad Soldermask Spacing" "6.7 MIL [SOLDERMASK_SPACING]" "0 MIL" "6.70 MIL" "DRC ERROR CLASS/SOLDERMASK_TOP" "[SmdPin] 85_MICRO_USB_DP_CON (<uTiL>cId824<uTiL>.2) (-974.83 1576.61)" "[SmdPin] 85_MICRO_USB_DP_CON (<uTiL>cId228<uTiL>.2) (-976.8 1574.64)" list(-976.800000 1574.640000) nil)@@@list("sky_zheng" "2013/09/13 11:01:22" nil "RDD_704_PC" "g1t-oxygen.10")@@@list("andy_lien" "2013/09/13 17:02:34" nil "ANDY_LIEN-PC" "g1t-oxygen.10") | list("[Package] BOTTOM" "78.Pad Soldermask to Pad Soldermask Spacing" "6.7 MIL [SOLDERMASK_SPACING]" "0 MIL" "6.70 MIL" "DRC ERROR CLASS/SOLDERMASK_TOP" "[SmdPin] 85_USB2_CPU_P1_DP (<uTiL>cId824<uTiL>.1) (-974.83 1527.39)" "[SmdPin] 85_USB2_CPU_P1_DP (<uTiL>cId228<uTiL>.1) (-976.8 1529.36)" list(-976.800000 1529.360000) nil)@@@list("sky_zheng" "2013/09/13 11:01:24" nil "RDD_704_PC" "g1t-oxygen.10")@@@list("andy_lien" "2013/09/13 17:02:36" nil "ANDY_LIEN-PC" "g1t-oxygen.10") | list("[Package] BOTTOM" "77.Pad Soldermask to Pad Soldermask Spacing" "6.7 MIL [SOLDERMASK_SPACING]" "0 MIL" "6.70 MIL" "DRC ERROR CLASS/SOLDERMASK_TOP" "[SmdPin] 85_MICRO_USB_DN_CON (<uTiL>cId824<uTiL>.3) (-953.17 1576.61)" "[SmdPin] 85_MICRO_USB_DN_CON (<uTiL>cId228<uTiL>.4) (-951.2 1574.64)" list(-951.200000 1574.640000) nil)@@@list("sky_zheng" "2013/09/13 11:01:23" nil "RDD_704_PC" "g1t-oxygen.10")@@@list("andy_lien" "2013/09/13 17:02:35" nil "ANDY_LIEN-PC" "g1t-oxygen.10") | list("[Package] BOTTOM" "79.Pad Soldermask to Pad Soldermask Spacing" "6.7 MIL [SOLDERMASK_SPACING]" "0 MIL" "6.70 MIL" "DRC ERROR CLASS/SOLDERMASK_TOP" "[SmdPin] 85_USB2_CPU_P1_DN (<uTiL>cId824<uTiL>.4) (-953.17 1527.39)" "[SmdPin] 85_USB2_CPU_P1_DN (<uTiL>cId228<uTiL>.3) (-951.2 1529.36)" list(-951.200000 1529.360000) nil)@@@list("sky_zheng" "2013/09/13 11:01:25" nil "RDD_704_PC" "g1t-oxygen.10")@@@list("andy_lien" "2013/09/13 17:02:37" nil "ANDY_LIEN-PC" "g1t-oxygen.10") | list("[Package] BOTTOM" "60.Pad Soldermask to Pad Soldermask Spacing" "6.7 MIL [SOLDERMASK_SPACING]" "0 MIL" "6.70 MIL" "DRC ERROR CLASS/SOLDERMASK_TOP" "[SmdPin] 85_HDMI_DATA2_DP_CON (<uTiL>cId2168<uTiL>.2) (-685.83 1454.61)" "[SmdPin] 85_HDMI_DATA2_DP_CON (<uTiL>cId2113<uTiL>.2) (-687.8 1452.64)" list(-687.800000 1452.640000) nil)@@@list("sky_zheng" "2013/09/13 11:01:06" nil "RDD_704_PC" "g1t-oxygen.10")@@@list("andy_lien" "2013/09/13 17:02:29" nil "ANDY_LIEN-PC" "g1t-oxygen.10") | list("[Package] BOTTOM" "62.Pad Soldermask to Pad Soldermask Spacing" "6.7 MIL [SOLDERMASK_SPACING]" "0 MIL" "6.70 MIL" "DRC ERROR CLASS/SOLDERMASK_TOP" "[SmdPin] 85_DDI0_TX0_DP_R (<uTiL>cId2168<uTiL>.1) (-685.83 1405.39)" "[SmdPin] 85_DDI0_TX0_DP_R (<uTiL>cId2113<uTiL>.1) (-687.8 1407.36)" list(-687.800000 1407.360000) nil)@@@list("sky_zheng" "2013/09/13 11:01:08" nil "RDD_704_PC" "g1t-oxygen.10")@@@list("andy_lien" "2013/09/13 17:02:30" nil "ANDY_LIEN-PC" "g1t-oxygen.10") | list("[Package] BOTTOM" "61.Pad Soldermask to Pad Soldermask Spacing" "6.7 MIL [SOLDERMASK_SPACING]" "0 MIL" "6.70 MIL" "DRC ERROR CLASS/SOLDERMASK_TOP" "[SmdPin] 85_HDMI_DATA2_DN_CON (<uTiL>cId2168<uTiL>.3) (-664.17 1454.61)" "[SmdPin] 85_HDMI_DATA2_DN_CON (<uTiL>cId2113<uTiL>.4) (-662.2 1452.64)" list(-662.200000 1452.640000) nil)@@@list("sky_zheng" "2013/09/13 11:01:07" nil "RDD_704_PC" "g1t-oxygen.10")@@@list("andy_lien" "2013/09/13 17:02:29" nil "ANDY_LIEN-PC" "g1t-oxygen.10") | list("[Package] BOTTOM" "64.Pad Soldermask to Pad Soldermask Spacing" "6.7 MIL [SOLDERMASK_SPACING]" "0 MIL" "6.70 MIL" "DRC ERROR CLASS/SOLDERMASK_TOP" "[SmdPin] 85_DDI0_TX0_DN_R (<uTiL>cId2168<uTiL>.4) (-664.17 1405.39)" "[SmdPin] 85_DDI0_TX0_DN_R (<uTiL>cId2113<uTiL>.3) (-662.2 1407.36)" list(-662.200000 1407.360000) nil)@@@list("sky_zheng" "2013/09/13 11:01:09" nil "RDD_704_PC" "g1t-oxygen.10")@@@list("andy_lien" "2013/09/13 17:02:30" nil "ANDY_LIEN-PC" "g1t-oxygen.10") | list("[Package] BOTTOM" "63.Pad Soldermask to Pad Soldermask Spacing" "6.7 MIL [SOLDERMASK_SPACING]" "0 MIL" "6.70 MIL" "DRC ERROR CLASS/SOLDERMASK_TOP" "[SmdPin] 85_HDMI_DATA1_DP_CON (<uTiL>cId2167<uTiL>.2) (-610.83 1454.61)" "[SmdPin] 85_HDMI_DATA1_DP_CON (<uTiL>cId2112<uTiL>.2) (-612.8 1452.64)" list(-612.800000 1452.640000) nil)@@@list("sky_zheng" "2013/09/13 11:01:09" nil "RDD_704_PC" "g1t-oxygen.10")@@@list("andy_lien" "2013/09/13 17:02:30" nil "ANDY_LIEN-PC" "g1t-oxygen.10") | list("[Package] BOTTOM" "65.Pad Soldermask to Pad Soldermask Spacing" "6.7 MIL [SOLDERMASK_SPACING]" "0 MIL" "6.70 MIL" "DRC ERROR CLASS/SOLDERMASK_TOP" "[SmdPin] 85_DDI0_TX1_DP_R (<uTiL>cId2167<uTiL>.1) (-610.83 1405.39)" "[SmdPin] 85_DDI0_TX1_DP_R (<uTiL>cId2112<uTiL>.1) (-612.8 1407.36)" list(-612.800000 1407.360000) nil)@@@list("sky_zheng" "2013/09/13 11:01:11" nil "RDD_704_PC" "g1t-oxygen.10")@@@list("andy_lien" "2013/09/13 17:02:31" nil "ANDY_LIEN-PC" "g1t-oxygen.10") | list("[Package] BOTTOM" "66.Pad Soldermask to Pad Soldermask Spacing" "6.7 MIL [SOLDERMASK_SPACING]" "0 MIL" "6.70 MIL" "DRC ERROR CLASS/SOLDERMASK_TOP" "[SmdPin] 85_HDMI_DATA1_DN_CON (<uTiL>cId2167<uTiL>.3) (-589.17 1454.61)" "[SmdPin] 85_HDMI_DATA1_DN_CON (<uTiL>cId2112<uTiL>.4) (-587.2 1452.64)" list(-587.200000 1452.640000) nil)@@@list("sky_zheng" "2013/09/13 11:01:10" nil "RDD_704_PC" "g1t-oxygen.10")@@@list("andy_lien" "2013/09/13 17:02:31" nil "ANDY_LIEN-PC" "g1t-oxygen.10") | list("[Package] BOTTOM" "67.Pad Soldermask to Pad Soldermask Spacing" "6.7 MIL [SOLDERMASK_SPACING]" "0 MIL" "6.70 MIL" "DRC ERROR CLASS/SOLDERMASK_TOP" "[SmdPin] 85_DDI0_TX1_DN_R (<uTiL>cId2167<uTiL>.4) (-589.17 1405.39)" "[SmdPin] 85_DDI0_TX1_DN_R (<uTiL>cId2112<uTiL>.3) (-587.2 1407.36)" list(-587.200000 1407.360000) nil)@@@list("sky_zheng" "2013/09/13 11:01:12" nil "RDD_704_PC" "g1t-oxygen.10")@@@list("andy_lien" "2013/09/13 17:02:31" nil "ANDY_LIEN-PC" "g1t-oxygen.10") | list("[Package] BOTTOM" "68.Pad Soldermask to Pad Soldermask Spacing" "6.7 MIL [SOLDERMASK_SPACING]" "0 MIL" "6.70 MIL" "DRC ERROR CLASS/SOLDERMASK_TOP" "[SmdPin] 85_HDMI_DATA0_DP_CON (<uTiL>cId2166<uTiL>.2) (-535.83 1454.61)" "[SmdPin] 85_HDMI_DATA0_DP_CON (<uTiL>cId2111<uTiL>.2) (-537.8 1452.64)" list(-537.800000 1452.640000) nil)@@@list("sky_zheng" "2013/09/13 11:01:14" nil "RDD_704_PC" "g1t-oxygen.10")@@@list("andy_lien" "2013/09/13 17:02:32" nil "ANDY_LIEN-PC" "g1t-oxygen.10") | list("[Package] BOTTOM" "69.Pad Soldermask to Pad Soldermask Spacing" "6.7 MIL [SOLDERMASK_SPACING]" "0 MIL" "6.70 MIL" "DRC ERROR CLASS/SOLDERMASK_TOP" "[SmdPin] 85_DDI0_TX2_DP_R (<uTiL>cId2166<uTiL>.1) (-535.83 1405.39)" "[SmdPin] 85_DDI0_TX2_DP_R (<uTiL>cId2111<uTiL>.1) (-537.8 1407.36)" list(-537.800000 1407.360000) nil)@@@list("sky_zheng" "2013/09/13 11:01:15" nil "RDD_704_PC" "g1t-oxygen.10")@@@list("andy_lien" "2013/09/13 17:02:32" nil "ANDY_LIEN-PC" "g1t-oxygen.10") | list("[Package] BOTTOM" "70.Pad Soldermask to Pad Soldermask Spacing" "6.7 MIL [SOLDERMASK_SPACING]" "0 MIL" "6.70 MIL" "DRC ERROR CLASS/SOLDERMASK_TOP" "[SmdPin] 85_HDMI_DATA0_DN_CON (<uTiL>cId2166<uTiL>.3) (-514.17 1454.61)" "[SmdPin] 85_HDMI_DATA0_DN_CON (<uTiL>cId2111<uTiL>.4) (-512.2 1452.64)" list(-512.200000 1452.640000) nil)@@@list("sky_zheng" "2013/09/13 11:01:14" nil "RDD_704_PC" "g1t-oxygen.10")@@@list("andy_lien" "2013/09/13 17:02:32" nil "ANDY_LIEN-PC" "g1t-oxygen.10") | list("[Package] BOTTOM" "72.Pad Soldermask to Pad Soldermask Spacing" "6.7 MIL [SOLDERMASK_SPACING]" "0 MIL" "6.70 MIL" "DRC ERROR CLASS/SOLDERMASK_TOP" "[SmdPin] 85_DDI0_TX2_DN_R (<uTiL>cId2166<uTiL>.4) (-514.17 1405.39)" "[SmdPin] 85_DDI0_TX2_DN_R (<uTiL>cId2111<uTiL>.3) (-512.2 1407.36)" list(-512.200000 1407.360000) nil)@@@list("sky_zheng" "2013/09/13 11:01:17" nil "RDD_704_PC" "g1t-oxygen.10")@@@list("andy_lien" "2013/09/13 17:02:33" nil "ANDY_LIEN-PC" "g1t-oxygen.10") | list("[Package] BOTTOM" "71.Pad Soldermask to Pad Soldermask Spacing" "6.7 MIL [SOLDERMASK_SPACING]" "0 MIL" "6.70 MIL" "DRC ERROR CLASS/SOLDERMASK_TOP" "[SmdPin] 85_HDMI_CLK_DP_CON (<uTiL>cId2165<uTiL>.2) (-460.83 1454.61)" "[SmdPin] 85_HDMI_CLK_DP_CON (<uTiL>cId2110<uTiL>.2) (-462.8 1452.64)" list(-462.800000 1452.640000) nil)@@@list("sky_zheng" "2013/09/13 11:01:18" nil "RDD_704_PC" "g1t-oxygen.10")@@@list("andy_lien" "2013/09/13 17:02:33" nil "ANDY_LIEN-PC" "g1t-oxygen.10") | list("[Package] BOTTOM" "74.Pad Soldermask to Pad Soldermask Spacing" "6.7 MIL [SOLDERMASK_SPACING]" "0 MIL" "6.70 MIL" "DRC ERROR CLASS/SOLDERMASK_TOP" "[SmdPin] 85_DDI0_TX3_DP_R (<uTiL>cId2165<uTiL>.1) (-460.83 1405.39)" "[SmdPin] 85_DDI0_TX3_DP_R (<uTiL>cId2110<uTiL>.1) (-462.8 1407.36)" list(-462.800000 1407.360000) nil)@@@list("sky_zheng" "2013/09/13 11:01:20" nil "RDD_704_PC" "g1t-oxygen.10")@@@list("andy_lien" "2013/09/13 17:02:34" nil "ANDY_LIEN-PC" "g1t-oxygen.10") | list("[Package] BOTTOM" "73.Pad Soldermask to Pad Soldermask Spacing" "6.7 MIL [SOLDERMASK_SPACING]" "0 MIL" "6.70 MIL" "DRC ERROR CLASS/SOLDERMASK_TOP" "[SmdPin] 85_HDMI_CLK_DN_CON (<uTiL>cId2165<uTiL>.3) (-439.17 1454.61)" "[SmdPin] 85_HDMI_CLK_DN_CON (<uTiL>cId2110<uTiL>.4) (-437.2 1452.64)" list(-437.200000 1452.640000) nil)@@@list("sky_zheng" "2013/09/13 11:01:19" nil "RDD_704_PC" "g1t-oxygen.10")@@@list("andy_lien" "2013/09/13 17:02:33" nil "ANDY_LIEN-PC" "g1t-oxygen.10") | list("[Package] BOTTOM" "75.Pad Soldermask to Pad Soldermask Spacing" "6.7 MIL [SOLDERMASK_SPACING]" "0 MIL" "6.70 MIL" "DRC ERROR CLASS/SOLDERMASK_TOP" "[SmdPin] 85_DDI0_TX3_DN_R (<uTiL>cId2165<uTiL>.4) (-439.17 1405.39)" "[SmdPin] 85_DDI0_TX3_DN_R (<uTiL>cId2110<uTiL>.3) (-437.2 1407.36)" list(-437.200000 1407.360000) nil)@@@list("sky_zheng" "2013/09/13 11:01:21" nil "RDD_704_PC" "g1t-oxygen.10")@@@list("andy_lien" "2013/09/13 17:02:34" nil "ANDY_LIEN-PC" "g1t-oxygen.10") | list("[Package] BOTTOM" "58.Pad Soldermask to Pad Soldermask Spacing" "6.7 MIL [SOLDERMASK_SPACING]" "0 MIL" "6.70 MIL" "DRC ERROR CLASS/SOLDERMASK_TOP" "[SmdPin] 85_USB2_DEBUG_B2B_DN (<uTiL>cId2163<uTiL>.4) (-337.76 -211.93)" "[SmdPin] 85_USB2_DEBUG_B2B_DN (<uTiL>cId2104<uTiL>.3) (-339.73 -213.9)" list(-339.730000 -213.900000) nil)@@@list("sky_zheng" "2013/09/13 11:01:04" nil "RDD_704_PC" "g1t-oxygen.10")@@@list("andy_lien" "2013/09/13 17:02:28" nil "ANDY_LIEN-PC" "g1t-oxygen.10") | list("[Package] BOTTOM" "59.Pad Soldermask to Pad Soldermask Spacing" "6.7 MIL [SOLDERMASK_SPACING]" "0 MIL" "6.70 MIL" "DRC ERROR CLASS/SOLDERMASK_TOP" "[SmdPin] 85_USB2_DEBUG_P0_DN (<uTiL>cId2163<uTiL>.3) (-337.76 -261.15)" "[SmdPin] 85_USB2_DEBUG_P0_DN (<uTiL>cId2104<uTiL>.4) (-339.73 -259.18)" list(-339.730000 -259.180000) nil)@@@list("sky_zheng" "2013/09/13 11:01:05" nil "RDD_704_PC" "g1t-oxygen.10")@@@list("andy_lien" "2013/09/13 17:02:29" nil "ANDY_LIEN-PC" "g1t-oxygen.10") | list("[Package] BOTTOM" "56.Pad Soldermask to Pad Soldermask Spacing" "6.7 MIL [SOLDERMASK_SPACING]" "0 MIL" "6.70 MIL" "DRC ERROR CLASS/SOLDERMASK_TOP" "[SmdPin] 85_USB2_DEBUG_B2B_DP (<uTiL>cId2163<uTiL>.1) (-316.1 -211.93)" "[SmdPin] 85_USB2_DEBUG_B2B_DP (<uTiL>cId2104<uTiL>.1) (-314.13 -213.9)" list(-314.130000 -213.900000) nil)@@@list("sky_zheng" "2013/09/13 11:01:03" nil "RDD_704_PC" "g1t-oxygen.10")@@@list("andy_lien" "2013/09/13 17:02:27" nil "ANDY_LIEN-PC" "g1t-oxygen.10") | list("[Package] BOTTOM" "57.Pad Soldermask to Pad Soldermask Spacing" "6.7 MIL [SOLDERMASK_SPACING]" "0 MIL" "6.70 MIL" "DRC ERROR CLASS/SOLDERMASK_TOP" "[SmdPin] 85_USB2_DEBUG_P0_DP (<uTiL>cId2163<uTiL>.2) (-316.1 -261.15)" "[SmdPin] 85_USB2_DEBUG_P0_DP (<uTiL>cId2104<uTiL>.2) (-314.13 -259.18)" list(-314.130000 -259.180000) nil)@@@list("sky_zheng" "2013/09/13 11:01:04" nil "RDD_704_PC" "g1t-oxygen.10")@@@list("andy_lien" "2013/09/13 17:02:28" nil "ANDY_LIEN-PC" "g1t-oxygen.10")
